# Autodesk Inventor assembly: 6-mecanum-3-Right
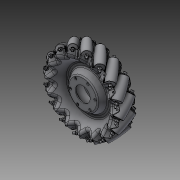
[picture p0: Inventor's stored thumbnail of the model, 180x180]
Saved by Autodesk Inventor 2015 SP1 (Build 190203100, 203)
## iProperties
Created: 2015-01
Part Number: 6-mecanum-3-Right
Document SubType Name: Assembly
Designer: TODD D MILLER
Mass: 589.67 g
Surface Area: 1360.11 cm^2
Volume: 181.889 cm^3
Density: 3.24192 g/cm^3
Title: 6-mecanum-3-Right.STEP
Description: STEP AP203
Creation Date: 2010-12-06
Sending System: SolidWorks 2010
Preprocessor: SwSTEP 2.0
Author: TODD D MILLER
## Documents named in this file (5)
- C:\Users\TODD D MILLER\Documents\GrabCAD\ElkLogics FRC\CAD Library\Mecanum wheels\6-mecanum-3-Right.iam
- C:\Users\TODD D MILLER\Documents\GrabCAD\ElkLogics FRC\CAD Library\Mecanum wheels\6-mecanum-3-Right\M3-Nylock-Nut_2.ipt
- C:\Users\TODD D MILLER\Documents\GrabCAD\ElkLogics FRC\CAD Library\Mecanum wheels\6-mecanum-3-Right\M - 3 x 0.5 x 50 SHCS_M - 3 x 0.5 x 50 SHCS.ipt
- C:\Users\TODD D MILLER\Documents\GrabCAD\ElkLogics FRC\CAD Library\Mecanum wheels\6-mecanum-3-Right\1_6.ipt
- C:\Users\TODD D MILLER\Documents\GrabCAD\ElkLogics FRC\CAD Library\Mecanum wheels\6-mecanum-3-Right\6 mecanum plate 3.ipt
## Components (50 placed, 50 different names)
1. M3-Nylock-Nut_2_1
2. M - 3 x 0.5 x 50 SHCS_M - 3 x 0.5 x 50 SHCS_2
3. 1_6_3
4. M - 3 x 0.5 x 50 SHCS_M - 3 x 0.5 x 50 SHCS_4
5. M - 3 x 0.5 x 50 SHCS_M - 3 x 0.5 x 50 SHCS_5
6. M - 3 x 0.5 x 50 SHCS_M - 3 x 0.5 x 50 SHCS_6
7. 1_6_7
8. 1_6_8
9. 1_6_9
10. M3-Nylock-Nut_2_10
11. M3-Nylock-Nut_2_11
12. M - 3 x 0.5 x 50 SHCS_M - 3 x 0.5 x 50 SHCS_12
13. M3-Nylock-Nut_2_13
14. M3-Nylock-Nut_2_14
15. 1_6_15
16. 1_6_16
17. 6 mecanum plate 3_17
18. M3-Nylock-Nut_2_18
19. M - 3 x 0.5 x 50 SHCS_M - 3 x 0.5 x 50 SHCS_19
20. M - 3 x 0.5 x 50 SHCS_M - 3 x 0.5 x 50 SHCS_20
21. M3-Nylock-Nut_2_21
22. 1_6_22
23. 1_6_23
24. M3-Nylock-Nut_2_24
25. M - 3 x 0.5 x 50 SHCS_M - 3 x 0.5 x 50 SHCS_25
26. M - 3 x 0.5 x 50 SHCS_M - 3 x 0.5 x 50 SHCS_26
27. 1_6_27
28. 1_6_28
29. 6 mecanum plate 3_29
30. M - 3 x 0.5 x 50 SHCS_M - 3 x 0.5 x 50 SHCS_30
31. M - 3 x 0.5 x 50 SHCS_M - 3 x 0.5 x 50 SHCS_31
32. 1_6_32
33. M3-Nylock-Nut_2_33
34. 1_6_34
35. M3-Nylock-Nut_2_35
36. M - 3 x 0.5 x 50 SHCS_M - 3 x 0.5 x 50 SHCS_36
37. M - 3 x 0.5 x 50 SHCS_M - 3 x 0.5 x 50 SHCS_37
38. 1_6_38
39. M3-Nylock-Nut_2_39
40. M3-Nylock-Nut_2_40
41. M3-Nylock-Nut_2_41
42. M - 3 x 0.5 x 50 SHCS_M - 3 x 0.5 x 50 SHCS_42
43. 1_6_43
44. M3-Nylock-Nut_2_44
45. M - 3 x 0.5 x 50 SHCS_M - 3 x 0.5 x 50 SHCS_45
46. M3-Nylock-Nut_2_46
47. 1_6_47
48. 1_6_48
49. M3-Nylock-Nut_2_49
50. M - 3 x 0.5 x 50 SHCS_M - 3 x 0.5 x 50 SHCS_50
